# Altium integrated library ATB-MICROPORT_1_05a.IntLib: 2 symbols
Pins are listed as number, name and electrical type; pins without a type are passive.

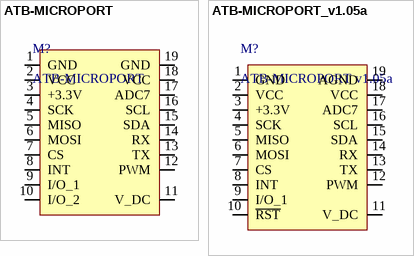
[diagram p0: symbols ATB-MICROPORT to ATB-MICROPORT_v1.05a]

## ATB-MICROPORT
designator M?
ver 1.05
footprint ATNEL-IO_V1.05A (ver 1.05a)
footprint ATNEL-IO_BRD_v1.05a (ver 1.05a)
pins: 1 GND, 2 VCC, 3 +3.3V, 4 SCK, 5 MISO, 6 MOSI, 7 CS, 8 INT, 9 I/O_1, 10 I/O_2, 11 V_DC, 12 PWM, 13 TX, 14 RX, 15 SDA, 16 SCL, 17 ADC7, 18 VCC, 19 GND

## ATB-MICROPORT_v1.05a
designator M?, comment ATB-MICROPORT v1.05a
ver 1.05a
footprint ATNEL-IO_BRD_v1.05a (ver 1.05a)
footprint ATNEL-IO_V1.05A (ver 1.05a)
pins: 1 GND, 2 VCC, 3 +3.3V, 4 SCK, 5 MISO, 6 MOSI, 7 CS, 8 INT, 9 I/O_1, 10 ~{RST}, 11 V_DC, 12 PWM, 13 TX, 14 RX, 15 SDA, 16 SCL, 17 ADC7, 18 VCC, 19 AGND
